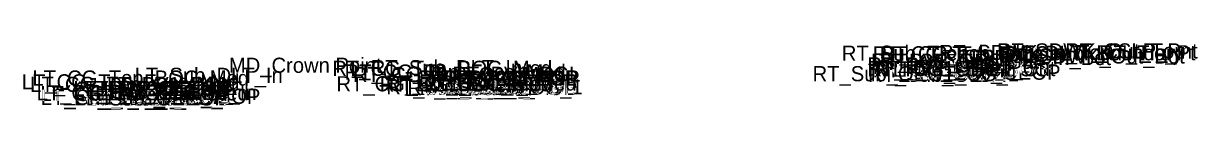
# Model space of a CAD drawing. Extents: x -26 to 6300, y -10 to 9528.
# Drawn here: x 2126 to 2203.7, y 9500.5 to 9504.9 of the extents above; entities that cross this region are included whole.
import ezdxf

# ---------------------------------------------------------------- set-up
doc = ezdxf.new("R2010")
doc.units = 0
doc.layers.add('Default', color=7, linetype='Continuous')

msp = doc.modelspace()

# ---------------------------------------------------------------- texts
at = {"layer": 'Default'}
for s, p in [('RT_Sub_Trench_Out_DLT', (2180.181, 9503.749)), ('RT_CG_Top_Face', (2182.225, 9503.709)), ('RT_CG_Top_BOC', (2182.694, 9503.709)), ('RT_SDWK_In_Top', (2186.62, 9503.799)), ('RT_SDWK_Out_Top', (2190.462, 9503.899)), ('RT_SDWK_Out_Bot', (2190.711, 9503.566)), ('Exterior Boundary', (2192.061, 9503.779)), ('RT_CSLP_Pnt', (2194.981, 9503.899)), ('RT_Tie_Pt', (2197.224, 9503.779)), ('MD_Crown Point', (2139.582, 9502.953)), ('RT_CG_Top_BOC_Med', (2146.431, 9502.753)), ('RT_Sub_DLT_In', (2148.978, 9502.795)), ('RT_PV2_OEOT', (2181.873, 9502.979)), ('RT_PV3_OEOT', (2181.873, 9502.729)), ('RT_PV1_OEOT', (2182.112, 9503.229)), ('RT_CG1_Shelf_Out', (2182.36, 9502.736)), ('RT_CG_Top_Gut', (2182.752, 9503.209)), ('RT_SDWK_In_Bot', (2186.869, 9503.466)), ('LT_CG_Top_BOC_Med', (2126.569, 9502.108)), ('LT_Sub_DLT_In', (2133.339, 9502.288)), ('RT_CG_Top_Face_Med', (2147.246, 9502.503)), ('RT_CG_Top_Gut_Med', (2147.8, 9502.337)), ('RT_PV2_OEEOP', (2152.167, 9502.109)), ('RT_PV2_IEEOP', (2152.928, 9502.109)), ('RT_PV2_PGL', (2154.145, 9502.109)), ('RT_PV1_PGL', (2154.385, 9502.359)), ('RT_Sub_OEOT_CG_1', (2178.247, 9502.396)), ('RT_Sub_OEOT', (2181.92, 9502.354)), ('RT_CG_Bot_IE', (2182.221, 9502.646)), ('RT_CG_Bot_BOC', (2182.97, 9502.721)), ('RT_Sub_OEOP', (2185.154, 9502.493)), ('LT_CG_Top_Face_Med', (2125.866, 9501.858)), ('LT_CG_Top_Gut_Med', (2126.418, 9501.692)), ('LT_CG_Bot_BOC_Med', (2126.846, 9501.131)), ('LT_PV2_OEEOP', (2129.285, 9501.419)), ('LT_PV3_OEEOP', (2129.285, 9501.169)), ('LT_PV2_IEEOP', (2130.046, 9501.419)), ('LT_CG1_Shelf_In', (2130.712, 9501.146)), ('LT_PV2_PGL', (2131.264, 9501.419)), ('LT_PV1_PGL', (2131.503, 9501.669)), ('RT_CG_Bot_BOC_Med', (2146.708, 9501.731)), ('RT_CG1_Shelf_In', (2149.573, 9501.716)), ('RT_CG_Bot_IE_Med', (2149.976, 9501.776)), ('RT_Sub_IEOT_CG_1', (2150.007, 9501.526)), ('RT_Sub_IEOP', (2151.404, 9501.458)), ('RT_PV3_OEEOP', (2152.167, 9501.859)), ('RT_Sub_OEEOP', (2152.214, 9501.484)), ('RT_Sub_IEEOP', (2152.975, 9501.484)), ('RT_Sub_PGL', (2154.192, 9501.484)), ('LT_CG_Bot_IE_Med', (2127.094, 9501.086)), ('LT_Sub_IEOT_CG_1', (2127.125, 9500.836)), ('LT_Sub_OEEOP', (2129.332, 9500.794)), ('LT_Sub_IEEOP', (2130.093, 9500.794)), ('LT_Sub_PGL', (2131.311, 9500.794)), ('LT_Sub_IEOP', (2133.043, 9500.903))]:
    msp.add_text(s, height=1, dxfattribs=at).set_placement(p)

doc.saveas('drawing.dxf')
